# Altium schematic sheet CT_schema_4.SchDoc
size 411 x 381 mm
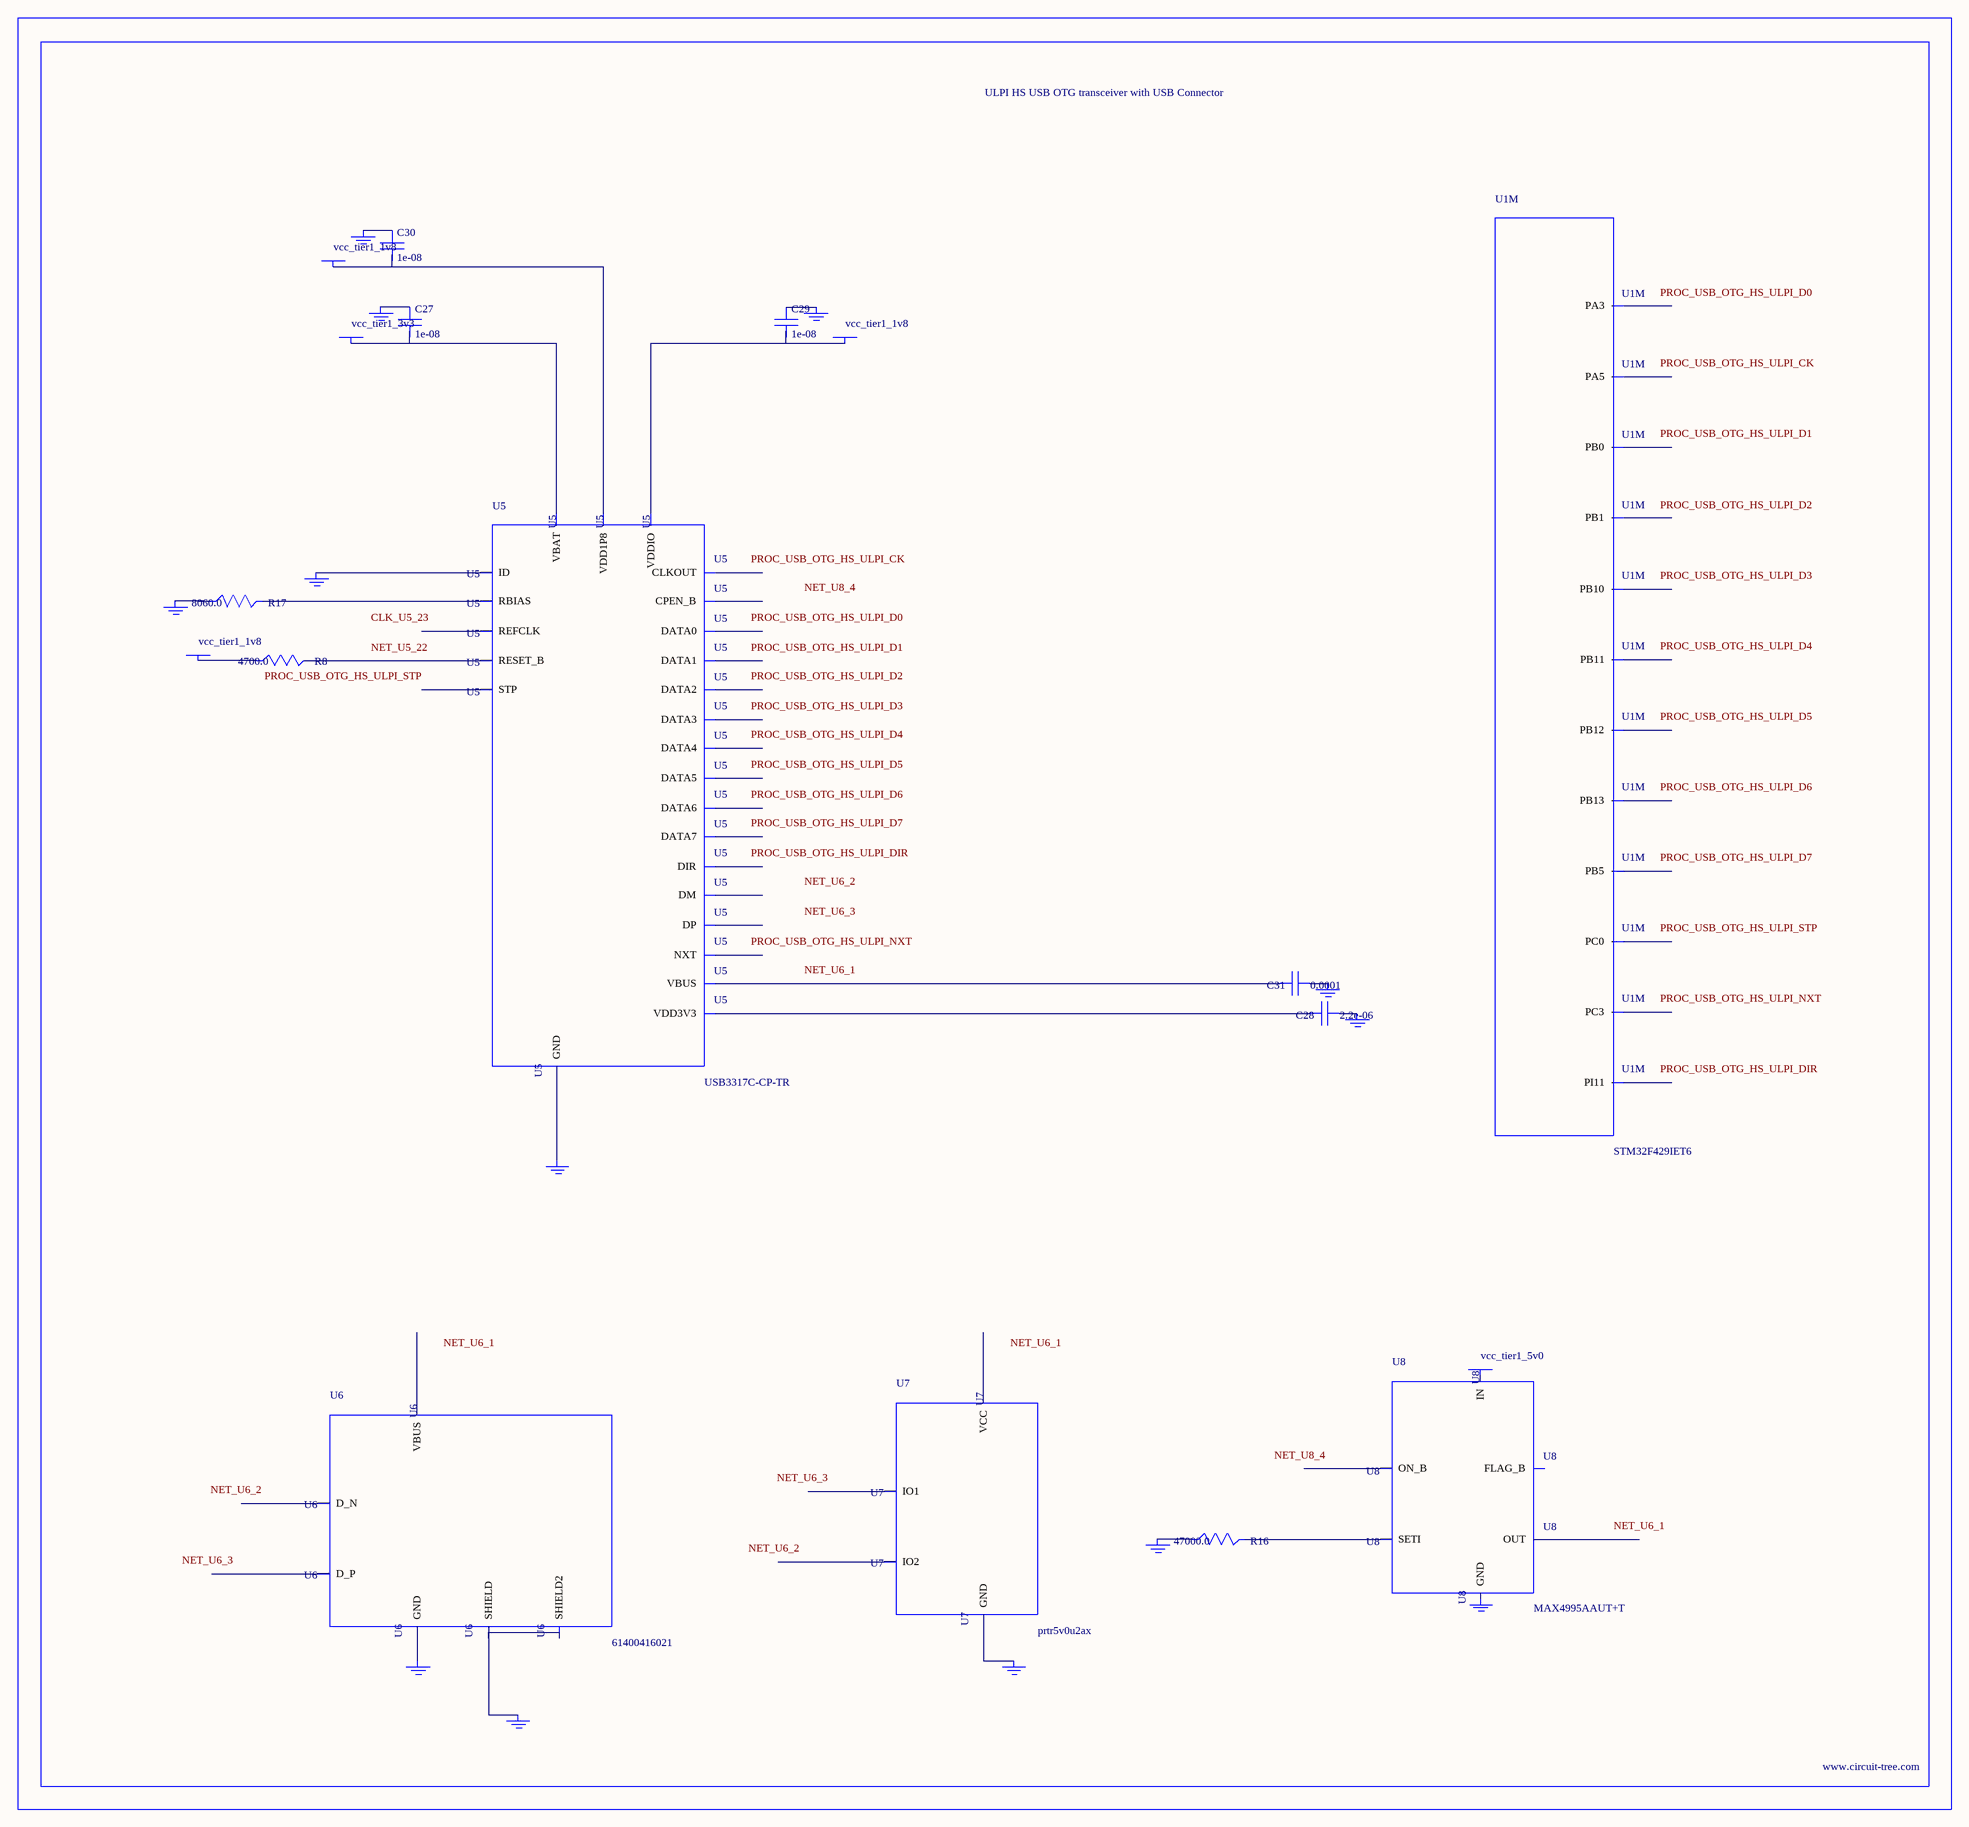
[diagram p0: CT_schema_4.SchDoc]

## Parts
BORDER3  (no value)
C27  1e-08  [C0402]
C28  2.2e-06  [C0603]
C29  1e-08  [C0402]
C30  1e-08  [C0402]
C31  0.0001  [R0603]
GND_INSTANCE_3_0  (no value)
GND_INSTANCE_3_1  (no value)
GND_INSTANCE_3_2  (no value)
GND_INSTANCE_3_3  (no value)
GND_INSTANCE_3_4  (no value)
GND_INSTANCE_3_5  (no value)
GND_INSTANCE_3_6  (no value)
GND_INSTANCE_3_7  (no value)
GND_INSTANCE_3_8  (no value)
GND_INSTANCE_3_9  (no value)
GND_INSTANCE_3_10  (no value)
GND_INSTANCE_3_11  (no value)
GND_INSTANCE_3_12  (no value)
POWER_INSTANCE_3_0  vcc_tier1_3v3
POWER_INSTANCE_3_1  vcc_tier1_1v8
POWER_INSTANCE_3_2  vcc_tier1_1v8
POWER_INSTANCE_3_3  vcc_tier1_1v8
POWER_INSTANCE_3_4  vcc_tier1_5v0
R8  4700.0  [R0603]
R16  47000.0  [R0603]
R17  8060.0  [R0603]
U1  STM32F429IET6  [LQFP176]  (part M of 13)
U5  USB3317C-CP-TR  [QFN-24]
U6  61400416021  [USB-A-H]
U7  prtr5v0u2ax  [SOT143B]
U8  MAX4995AAUT+T  [SOT-23-6]

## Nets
NetC27_1: C27.1 GND_INSTANCE_3_2.0(GND)
NetC27_2: C27.2 POWER_INSTANCE_3_0.0(PWR) U5.3(VBAT)
NetC28_1: C28.1 GND_INSTANCE_3_3.0(GND)
NetC28_2: C28.2 U5.4(VDD3V3)
NetC29_1: C29.1 GND_INSTANCE_3_4.0(GND)
NetC29_2: C29.2 POWER_INSTANCE_3_1.0(PWR) U5.17(VDDIO)
NetC30_1: C30.1 GND_INSTANCE_3_5.0(GND)
NetC30_2: C30.2 POWER_INSTANCE_3_2.0(PWR) U5.21(VDD1P8)
NetC31_1: C31.1 GND_INSTANCE_3_1.0(GND)
NetC31_2: C31.2 U5.2(VBUS)
NetGND_INSTANCE_3_0_0: GND_INSTANCE_3_0.0(GND) U5.1(ID)
NetGND_INSTANCE_3_6_0: GND_INSTANCE_3_6.0(GND) R17.1
NetGND_INSTANCE_3_7_0: GND_INSTANCE_3_7.0(GND) U5.25(GND)
NetGND_INSTANCE_3_8_0: GND_INSTANCE_3_8.0(GND) U6.5(SHIELD) U6.6(SHIELD2)
NetGND_INSTANCE_3_9_0: GND_INSTANCE_3_9.0(GND) U6.4(GND)
NetGND_INSTANCE_3_10_0: GND_INSTANCE_3_10.0(GND) U7.1(GND)
NetGND_INSTANCE_3_11_0: GND_INSTANCE_3_11.0(GND) R16.1
NetPOWER_INSTANCE_3_3_0: POWER_INSTANCE_3_3.0(PWR) R8.1
NetR8_2: R8.2 U5.22(RESET_B)
NetR16_2: R16.2 U8.3(SETI)
NetR17_2: R17.2 U5.24(RBIAS)

Not connected (* = marked no-connect by the designer): GND_INSTANCE_3_12 0(GND); POWER_INSTANCE_3_4 0(PWR); U1 13(PI11) 32(PC0) 35(PC3) 47(PA3) 51(PA5) 56(PB0) 57(PB1) 79(PB10) 80(PB11) 92(PB12) 93(PB13) 163(PB5); U5 5(DM) 6(DP) 7(CPEN_B) 8(DATA7) 9(DATA6) 10(DATA5) 11(DATA4) 12(CLKOUT) 13(DATA3) 14(DATA2) 15(DATA1) 16(DATA0) 18(NXT) 19(DIR) 20(STP) 23(REFCLK); U6 1(VBUS) 2(D_N) 3(D_P); U7 2(IO1) 3(IO2) 4(VCC); U8 1(OUT) 2(GND) 4(ON_B) 5(IN) 6(FLAG_B)

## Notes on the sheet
- Labels drawn without touching a wire or pin: CLK_U5_23, NET_U5_22, NET_U6_1, NET_U6_2, NET_U6_3, NET_U8_4, PROC_USB_OTG_HS_ULPI_CK, PROC_USB_OTG_HS_ULPI_D0, PROC_USB_OTG_HS_ULPI_D1, PROC_USB_OTG_HS_ULPI_D2, PROC_USB_OTG_HS_ULPI_D3, PROC_USB_OTG_HS_ULPI_D4, PROC_USB_OTG_HS_ULPI_D5, PROC_USB_OTG_HS_ULPI_D6, PROC_USB_OTG_HS_ULPI_D7, PROC_USB_OTG_HS_ULPI_DIR, PROC_USB_OTG_HS_ULPI_NXT, PROC_USB_OTG_HS_ULPI_STP

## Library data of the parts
BORDER3 = BORDER_PAGE3
C27 C29 C30 = C0402C103K3RAC
C28 = C0603C225K8RACTU
C31 = C31
GND_INSTANCE_3_0-GND_INSTANCE_3_12 = GND
POWER_INSTANCE_3_0-POWER_INSTANCE_3_4 = PWR
R8 = RC0603JR-074K7L
R16 = RC0603JR-0747KL
R17 = ERJ-3EKF8061V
